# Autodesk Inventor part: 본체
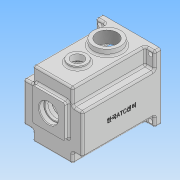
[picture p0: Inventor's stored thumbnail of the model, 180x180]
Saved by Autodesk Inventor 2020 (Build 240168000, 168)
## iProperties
Created: 2022-01
Part Number: 본체
Material: 일반
Document SubType Name: Modeling
Designer: user
Density: 1 g/cm^3
Appearance: 기본값
Author: user
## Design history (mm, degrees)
sketch "스케치1"
  geometry: L1 (-49, 55)-(49, 55); L2 (49, 55)-(49, -55); L3 (49, -55)-(-49, -55); L4 (-49, -55)-(-49, 55); L5 (-49, 55)-(49, -55); L6 (49, 55)-(-49, -55); 1 further point
  constraints: 12 end point, 2 midpoint, 2 parallel, 1 horizontal, 1 perpendicular
  dimensions: "d0" = 98 distance of L1.start L1.end; "d1" = 110 distance of L3.end L1.start
extrude "돌출1" new body sketch "스케치1" distance "d2" = 130; taper "d3" = 0 deg
sketch "스케치2"
  geometry: L1 (49, 55)-(-49, 55) reference; L2 (-49, 55)-(-49, -55) reference; L3 (-49, -55)-(49, -55) reference; L4 (49, -55)-(49, 55) reference; L5 (-49, 55)-(-33, 55); L6 (-33, 55)-(-33, 28); L7 (-33, 28)-(-49, 28); L8 (-49, 28)-(-49, 55); L9 (49, 55)-(-49, 55) reference; L10 (0, 55)-(0, 0); L11 (0, 0)-(49, 0); L12 (49, -55)-(49, 55) reference; L13 (49, 55)-(33, 55); L14 (33, 55)-(33, 28); L15 (33, 28)-(49, 28); L16 (49, 28)-(49, 55); L17 (-49, 55)-(-49, -55) reference; L18 (-49, -55)-(-33, -55); L19 (-33, -55)-(-33, -38); L20 (-33, -38)-(-49, -38); L21 (-49, -38)-(-49, -55); L22 (49, -55)-(33, -55); L23 (33, -55)-(33, -38); L24 (33, -38)-(49, -38); L25 (49, -38)-(49, -55); 8 further points
  constraints: 36 end point, 6 parallel, 3 horizontal, 3 perpendicular, 3 symmetric about line, 2 midpoint, 1 vertical
  dimensions: "d4" = 16 distance of L1.end L5.end; "d5" = 27 distance of L5.end L6.end; "d6" = 16 distance of L19.end L20.end; "d7" = 16 distance of L23.end L24.end; "d8" = 17 distance of L18.end L19.end; "d9" = 17 distance of L22.end L23.end
extrude "돌출2" cut sketch "스케치2" distance "d10" = 120; taper "d11" = 0 deg
node "작업 평면1"
sketch "스케치4"
  geometry: L1 (98, 0)-(0, 0) reference; C1 r 22.5 at (49, -40); 1 further point
  constraints: 1 centre point, 1 vertical alignment
  dimensions: "d17" = 45 diameter of C1; "d19" = 40 distance from line of C1.centre L1
extrude "돌출4" join sketch "스케치4" stored distance "d21" = 7; taper "d22" = 0 deg
node "작업 평면2"
sketch "스케치5"
  geometry: C1 r 15 at (49, -89); C2 r 22.5 at (49, -40) reference; 1 further point
  constraints: 1 centre point, 1 vertical alignment
  dimensions: "d24" = 30 diameter of C1; "d25" = 49 distance of C1.centre C2.centre
extrude "돌출5" join sketch "스케치5" stored distance "d26" = 7; taper "d27" = 0 deg
sketch "스케치6"
  geometry: L1 (-49, 55)-(49, 55) reference; L2 (49, -55)-(-49, -55) reference; L3 (-23, 45)-(23, 45); L4 (23, 45)-(23, -5); L5 (23, -5)-(-23, -5); L6 (-23, -5)-(-23, 45); C1 r 42 at (0, -5); 6 further points
  constraints: 8 end point, 3 midpoint, 2 parallel, 2 vertical alignment, 1 centre point, 1 coincident, 1 horizontal, 1 perpendicular
  dimensions: "d28" = 50 distance from line of C1.centre L2; "d29" = 84 diameter of C1; "d30" = 50 distance from line of L3 C1.centre; "d31" = 46 distance of L3.start L3.end
extrude "돌출6" cut sketch "스케치6" distance "d32" = 121; taper "d33" = 0 deg
sketch "스케치7"
  geometry: L1 (23, 45)-(23, 30.143) reference; L2 (-23, 45)-(23, 45) reference; L3 (-23, 30.143)-(-23, 45) reference; L4 (26, 48)-(26, 31.729); L5 (-26, 31.729)-(-26, 48); L6 (-26, 48)-(26, 48); A1 r 42 centre (0, -5) between (-23, 30.143) and (23, 30.143) reference; A2 r 45 centre (0, -5) between (-26, 31.729) and (26, 31.729)
  constraints: 6 end point, 2 point on circle, 1 centre point, 3 other
  dimensions: "d38" = 3 distance between parallel lines of L2 L6
extrude "돌출7" cut sketch "스케치7" distance "d39" = 9; taper "d40" = 0 deg
sketch "스케치8"
  geometry: L1 (-27, 33)-(27, 33); L2 (27, 33)-(27, -21); L3 (27, -21)-(-27, -21); L4 (-27, -21)-(-27, 33); L5 (-27, 33)-(27, -21); L6 (27, 33)-(-27, -21); L7 (-33, -55)-(33, -55) reference; 3 further points
  constraints: 12 end point, 3 midpoint, 2 parallel, 1 horizontal, 1 perpendicular, 1 vertical alignment
  dimensions: "d41" = 54 distance of L2.end L3.end; "d42" = 54 distance of L1.end L2.end; "d43" = 61 distance from line of L7 point (0, 6)
extrude "돌출8" join sketch "스케치8" distance "d44" = 7; taper "d45" = 0 deg
sketch "스케치9"
  geometry: C1 r 22.5 at (0, 0) reference; 2 further points
  constraints: 1 coincident
hole "구멍1" sketch "스케치9" at (0, 0) diameter "d46" = 33.376; stored, may be unused: countersink angle "d50" = 90 deg, drill point angle "d52" = 118 deg; dims "d47" = 58, "d48" = 4, "d49" = 2, "d51" = 67.55
sketch "스케치10"
  geometry: C1 r 15 at (0, 0) reference; 2 further points
  constraints: 1 coincident
hole "구멍2" sketch "스케치10" at (0, 0) diameter "d53" = 20; stored, may be unused: countersink angle "d57" = 90 deg, drill point angle "d59" = 0 deg; dims "d54" = 58, "d55" = 4, "d56" = 2, "d58" = 63.3
sketch "스케치11"
  geometry: L1 (56, 9)-(56, -111) reference; L2 (56, -111)-(72, -111) reference; L3 (72, -121)-(72, -111) reference; L4 (72, -121)-(-26, -121) reference; L5 (-26, -121)-(-26, -111) reference; L6 (-26, -111)-(-10, -111) reference; L7 (-10, -111)-(-10, 9) reference; L8 (56, 9)-(-10, 9) reference; C1 r 15 at (23, -32) reference; C2 r 22.5 at (23, -81) reference; C3 r 15 at (23, -32); 1 further point
  constraints: 1 centre point, 1 coincident
  dimensions: "d60" = 30 diameter of C3
extrude "돌출9" cut sketch "스케치11" distance "d61" = 5; taper "d62" = 0 deg
sketch "스케치14"
  geometry: L1 (-33, 55)-(33, 55) reference; L2 (33, -55)-(-33, -55) reference; C1 r 21 at (0, 6); C2 r 15 at (0, -25); 4 further points
  constraints: 2 centre point, 2 vertical alignment, 1 midpoint
  dimensions: "d73" = 42 diameter of C1; "d74" = 61 distance from line of C1.centre L2; "d75" = 30 diameter of C2; "d76" = 31 distance of C2.centre C1.centre
extrude "돌출11" join sketch "스케치14" distance "d78" = 7; taper "d79" = 0 deg
sketch "스케치15"
  geometry: A1 r 15 centre (0, -25) between (-8.978, -12.984) and (8.978, -12.984) reference; A2 r 21 centre (0, 6) between (8.978, -12.984) and (-8.978, -12.984) reference; 1 further point
hole "구멍4" sketch "스케치15" at (0, 6) diameter "d80" = 28; stored, may be unused: countersink angle "d84" = 90 deg, drill point angle "d86" = 0 deg; dims "d81" = 58, "d82" = 35, "d83" = 10, "d85" = 20
sketch "스케치16"
  geometry: C1 r 14 at (0, 6) reference; 1 further point
hole "구멍5" sketch "스케치16" at (0, 6) diameter "d87" = 32; stored, may be unused: countersink angle "d91" = 90 deg, drill point angle "d93" = 0 deg; dims "d88" = 58, "d89" = 35, "d90" = 10, "d92" = 8.3
sketch "스케치17"
  geometry: C1 r 17.5 at (0, 6) reference; A1 r 15 centre (0, -25) between (-8.978, -12.984) and (8.978, -12.984) reference; A2 r 21 centre (0, 6) between (8.978, -12.984) and (-8.978, -12.984) reference; 1 further point
hole "구멍6" sketch "스케치17" at (0, -25) diameter "d94" = 19; stored, may be unused: countersink angle "d98" = 90 deg, drill point angle "d100" = 0 deg; dims "d95" = 58, "d96" = 22, "d97" = 7, "d99" = 10
sketch "스케치18"
  geometry: L1 (-36, -5)-(36, -5); L2 (-36, -9)-(-41.809, -9); L3 (-35.778, -1.006)-(-41.81, -1.006); L4 (35.778, -1.006)-(41.81, -1.006); L5 (35.778, -8.994)-(41.81, -8.994); A1 r 42 centre (0, -5) between (-23, 30.143) and (23, 30.143) reference; A2 r 36 centre (0, -5) between (-36, -5) and (36, -5); A3 r 4 centre (-36, -5) between (-36, -9) and (-35.778, -1.006); A4 r 4 centre (36, -5) between (35.778, -1.006) and (35.778, -8.994); 5 further points
  constraints: 13 point on circle, 10 end point, 5 horizontal, 4 coincident, 3 centre point, 1 midpoint, 1 tangent
  dimensions: "d101" = 72 diameter of A2; "d102" = 8 diameter of A3; "d103" = 8 diameter of A4
extrude "돌출12" join sketch "스케치18" stored distance "d104" = 7; taper "d105" = 0 deg
sketch "스케치20"
  geometry: A1 r 4 centre (-36, -5) between (-36, -9) and (-36.222, -1.006) reference; A2 r 4 centre (36, -5) between (36.222, -1.006) and (36.222, -8.994) reference; 3 further points
  constraints: 2 coincident
hole "구멍7" sketch "스케치20" at (-36, -5), (36, -5) diameter "d106" = 3.242; stored, may be unused: countersink angle "d110" = 90 deg, drill point angle "d112" = 118 deg; dims "d107" = 7, "d108" = 22, "d109" = 7, "d111" = 9
fillet "모깎기1" dims "d113" = 3
fillet "모깎기2" dims "d114" = 3
fillet "모깎기3" dims "d115" = 3
fillet "모깎기4" dims "d116" = 3
fillet "모깎기5" dims "d117" = 3
fillet "모깎기6" dims "d118" = 3
fillet "모깎기7" dims "d119" = 3
fillet "모깎기8" dims "d120" = 3
fillet "모깎기9" dims "d124" = 0.3
fillet "모깎기10" dims "d125" = 3
fillet "모깎기11" dims "d129" = 6
fillet "모깎기12" dims "d130" = 3
fillet "모깎기13" dims "d134" = 3
fillet "모깎기14" dims "d135" = 3
fillet "모깎기15" dims "d136" = 3
fillet "모깎기16" dims "d137" = 3
fillet "모깎기17" dims "d138" = 3
chamfer "모따기4" distance "d139" = 1; stored, may be unused: second distance "d140" = 2, angle "d141" = 30 deg
chamfer "모따기5" distance "d142" = 1; stored, may be unused: second distance "d143" = 2, angle "d144" = 30 deg
sketch "스케치21" dims "d154" = 10
  geometry: L1 (-49, -52)-(-49, 52) reference; L2 (-46, 55)-(46, 55) reference; 5 further points
  constraints: 1 horizontal, 2 other
  dimensions: "d145" = 7 distance from line of point (-42, 48) L1; "d146" = 7 distance from line of point (-42, 48) L2; "d147" = 7 distance from line of point (-42, -48) L1; "d148" = 96 distance of point (-42, -48) point (-42, 48); "d151" = 84 distance of point (-42, 48) point (42, 48)
hole "구멍8" sketch "스케치21" at (-42, 48), (-42, -48), (42, 48), (42, -48) diameter "d156" = 7; stored, may be unused: countersink angle "d160" = 90 deg, drill point angle "d162" = 0 deg; dims "d157" = 8, "d158" = 22, "d159" = 7, "d161" = 10
sketch "스케치22"
  geometry: L1 (-3, 87)-(-3, 66) reference; L2 (114, 90)-(0, 90) reference; L3 (114, 63)-(0, 63) reference; 2 further points
  constraints: 1 other
  dimensions: "d163" = 65 distance from line of point (62, 30) L1; "d165" = 27 distance between parallel lines of L3 L2 (derived); "d166" = 33 distance from line of point (62, 30) L3
feature "엠보싱1" sketch "스케치22" dims "d4" = 16, "d5" = 27, "d167" = 0.5, "d168" = 0
fillet "모깎기18" dims "d169" = 6
chamfer "모따기6" distance "d170" = 1; stored, may be unused: second distance "d171" = 2, angle "d172" = 30 deg
fillet "모깎기20" dims "d174" = 0.3
chamfer "모따기7" distance "d175" = 0.8; stored, may be unused: second distance "d176" = 2, angle "d177" = 60 deg
node "솔리드1"
node "투영된 루프1"
node "투영된 루프2"
node "투영된 루프3"
node "투영된 루프4"
node "투영된 루프7"
node "투영된 루프8"
feature "A9D066F2-1C7D-4E18-AEED-F7BC21143FA4" dims "d53" = 20, "d54" = 58, "d55" = 4, "d56" = 2, "d57" = 90 deg, "d58" = 63.3, "d59" = 0
other parameters: "d23" = 5
